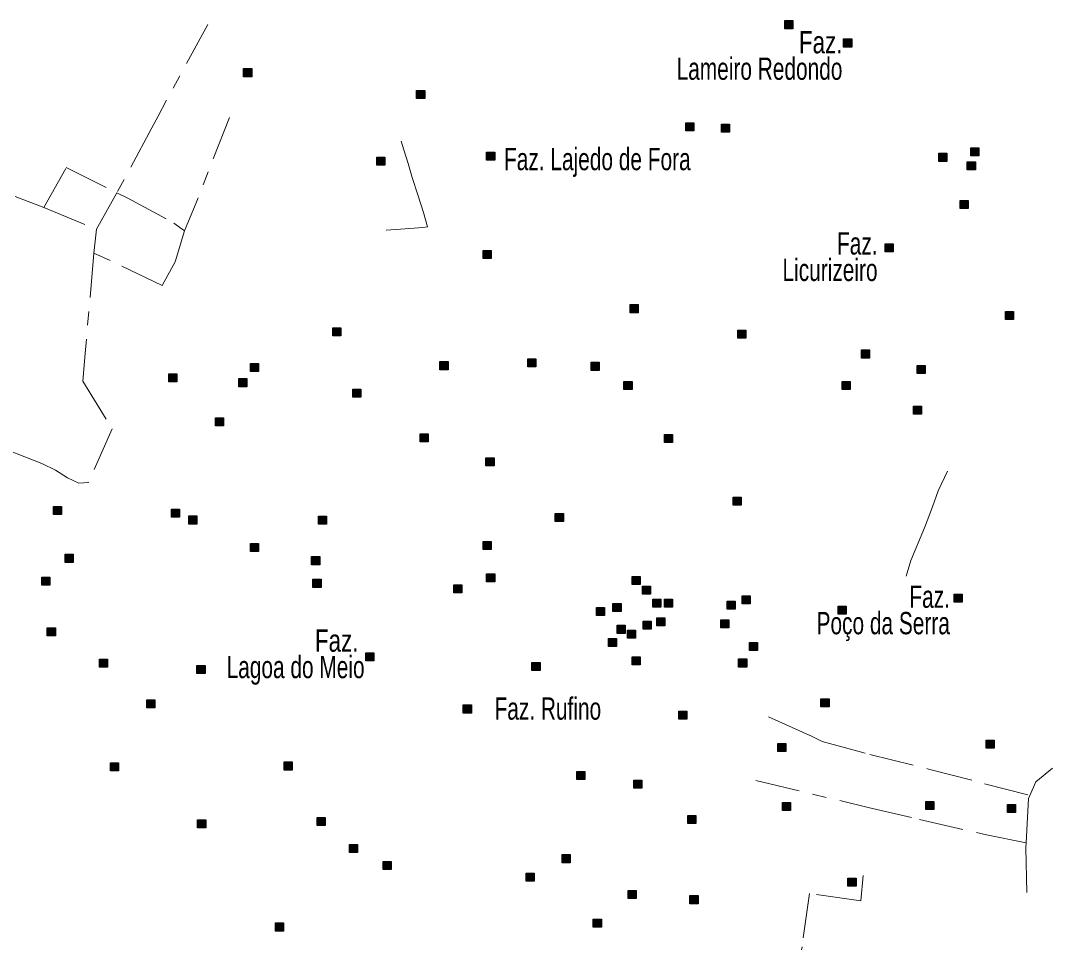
# Model space of a CAD drawing. Extents: x 445.4 to 500, y 8728.7 to 8784.
# Drawn here: x 492.59 to 500, y 8746.14 to 8752.76 of the extents above; entities that cross this region are included whole.
import ezdxf
from ezdxf.enums import TextEntityAlignment as Align

# ---------------------------------------------------------------- set-up
doc = ezdxf.new("R2010")
doc.units = 0
doc.header["$LTSCALE"] = 0.064
doc.linetypes.add('DOT_DASHED', pattern=[7.7, 5, -1.2, 0.3, -1.2])
doc.layers.add('2', color=7, linetype='Continuous', lineweight=25)
doc.layers.add('22', color=7, linetype='DOT_DASHED', lineweight=13)
doc.layers.add('61', color=7, linetype='Continuous')

msp = doc.modelspace()

# ---------------------------------------------------------------- hatches: boundary and pattern name
at = {"layer": '2'}
for points in [[(498.0778, 8752.7596), (498.1358, 8752.7596), (498.1358, 8752.7016), (498.0778, 8752.7016)], [(498.501, 8752.6281), (498.559, 8752.6281), (498.559, 8752.5701), (498.501, 8752.5701)], [(494.1928, 8752.4151), (494.2508, 8752.4151), (494.2508, 8752.3571), (494.1928, 8752.3571)], [(495.435, 8752.2582), (495.493, 8752.2582), (495.493, 8752.2002), (495.435, 8752.2002)], [(497.3673, 8752.0264), (497.4253, 8752.0264), (497.4253, 8751.9684), (497.3673, 8751.9684)], [(497.6236, 8752.0166), (497.6816, 8752.0166), (497.6816, 8751.9586), (497.6236, 8751.9586)], [(495.9378, 8751.8144), (495.9958, 8751.8144), (495.9958, 8751.7564), (495.9378, 8751.7564)], [(499.1851, 8751.8069), (499.2431, 8751.8069), (499.2431, 8751.7489), (499.1851, 8751.7489)], [(499.415, 8751.847), (499.473, 8751.847), (499.473, 8751.789), (499.415, 8751.789)], [(495.1491, 8751.7799), (495.2071, 8751.7799), (495.2071, 8751.7219), (495.1491, 8751.7219)], [(499.389, 8751.7454), (499.447, 8751.7454), (499.447, 8751.6874), (499.389, 8751.6874)], [(499.3374, 8751.468), (499.3954, 8751.468), (499.3954, 8751.41), (499.3374, 8751.41)], [(498.7985, 8751.1572), (498.8565, 8751.1572), (498.8565, 8751.0992), (498.7985, 8751.0992)], [(495.9132, 8751.1091), (495.9712, 8751.1091), (495.9712, 8751.0511), (495.9132, 8751.0511)], [(496.968, 8750.7195), (497.026, 8750.7195), (497.026, 8750.6615), (496.968, 8750.6615)], [(499.663, 8750.6703), (499.721, 8750.6703), (499.721, 8750.6123), (499.663, 8750.6123)], [(494.833, 8750.5535), (494.891, 8750.5535), (494.891, 8750.4955), (494.833, 8750.4955)], [(497.7419, 8750.5371), (497.7999, 8750.5371), (497.7999, 8750.4791), (497.7419, 8750.4791)], [(498.6292, 8750.394), (498.6872, 8750.394), (498.6872, 8750.336), (498.6292, 8750.336)], [(495.6026, 8750.3102), (495.6606, 8750.3102), (495.6606, 8750.2522), (495.6026, 8750.2522)], [(496.2336, 8750.3299), (496.2916, 8750.3299), (496.2916, 8750.2719), (496.2336, 8750.2719)], [(494.2421, 8750.2965), (494.3001, 8750.2965), (494.3001, 8750.2385), (494.2421, 8750.2385)], [(496.6871, 8750.3053), (496.7451, 8750.3053), (496.7451, 8750.2473), (496.6871, 8750.2473)], [(499.0283, 8750.2826), (499.0863, 8750.2826), (499.0863, 8750.2246), (499.0283, 8750.2246)], [(493.6555, 8750.2225), (493.7135, 8750.2225), (493.7135, 8750.1645), (493.6555, 8750.1645)], [(494.1583, 8750.188), (494.2163, 8750.188), (494.2163, 8750.13), (494.1583, 8750.13)], [(496.9237, 8750.1672), (496.9817, 8750.1672), (496.9817, 8750.1092), (496.9237, 8750.1092)], [(498.4912, 8750.1672), (498.5492, 8750.1672), (498.5492, 8750.1092), (498.4912, 8750.1092)], [(494.9766, 8750.1129), (495.0346, 8750.1129), (495.0346, 8750.0549), (494.9766, 8750.0549)], [(499.0028, 8749.9906), (499.0608, 8749.9906), (499.0608, 8749.9326), (499.0028, 8749.9326)], [(493.9907, 8749.9068), (494.0487, 8749.9068), (494.0487, 8749.8488), (493.9907, 8749.8488)], [(495.4597, 8749.7924), (495.5177, 8749.7924), (495.5177, 8749.7344), (495.4597, 8749.7344)], [(497.2145, 8749.7874), (497.2725, 8749.7874), (497.2725, 8749.7294), (497.2145, 8749.7294)], [(495.9329, 8749.6198), (495.9909, 8749.6198), (495.9909, 8749.5618), (495.9329, 8749.5618)], [(492.8274, 8749.2707), (492.8854, 8749.2707), (492.8854, 8749.2127), (492.8274, 8749.2127)], [(497.7081, 8749.337), (497.7661, 8749.337), (497.7661, 8749.279), (497.7081, 8749.279)], [(493.6752, 8749.2509), (493.7332, 8749.2509), (493.7332, 8749.1929), (493.6752, 8749.1929)], [(493.7985, 8749.2016), (493.8565, 8749.2016), (493.8565, 8749.1436), (493.7985, 8749.1436)], [(494.7302, 8749.2006), (494.7882, 8749.2006), (494.7882, 8749.1426), (494.7302, 8749.1426)], [(496.4307, 8749.2203), (496.4887, 8749.2203), (496.4887, 8749.1623), (496.4307, 8749.1623)], [(494.2421, 8749.0043), (494.3001, 8749.0043), (494.3001, 8748.9463), (494.2421, 8748.9463)], [(495.9132, 8749.0181), (495.9712, 8749.0181), (495.9712, 8748.9601), (495.9132, 8748.9601)], [(492.9115, 8748.9265), (492.9695, 8748.9265), (492.9695, 8748.8685), (492.9115, 8748.8685)], [(494.6809, 8748.9096), (494.7389, 8748.9096), (494.7389, 8748.8516), (494.6809, 8748.8516)], [(492.7436, 8748.7627), (492.8016, 8748.7627), (492.8016, 8748.7047), (492.7436, 8748.7047)], [(495.9378, 8748.7863), (495.9958, 8748.7863), (495.9958, 8748.7283), (495.9378, 8748.7283)], [(496.9828, 8748.7666), (497.0408, 8748.7666), (497.0408, 8748.7086), (496.9828, 8748.7086)], [(494.6907, 8748.7469), (494.7487, 8748.7469), (494.7487, 8748.6889), (494.6907, 8748.6889)], [(495.7012, 8748.7074), (495.7592, 8748.7074), (495.7592, 8748.6494), (495.7012, 8748.6494)], [(497.0568, 8748.6975), (497.1148, 8748.6975), (497.1148, 8748.6395), (497.0568, 8748.6395)], [(497.1307, 8748.6038), (497.1887, 8748.6038), (497.1887, 8748.5458), (497.1307, 8748.5458)], [(497.2145, 8748.6038), (497.2725, 8748.6038), (497.2725, 8748.5458), (497.2145, 8748.5458)], [(497.7715, 8748.6285), (497.8295, 8748.6285), (497.8295, 8748.5705), (497.7715, 8748.5705)], [(499.2946, 8748.6402), (499.3526, 8748.6402), (499.3526, 8748.5822), (499.2946, 8748.5822)], [(496.7265, 8748.5447), (496.7845, 8748.5447), (496.7845, 8748.4867), (496.7265, 8748.4867)], [(496.8448, 8748.5742), (496.9028, 8748.5742), (496.9028, 8748.5162), (496.8448, 8748.5162)], [(497.6649, 8748.5898), (497.7229, 8748.5898), (497.7229, 8748.5318), (497.6649, 8748.5318)], [(498.4616, 8748.5545), (498.5196, 8748.5545), (498.5196, 8748.4965), (498.4616, 8748.4965)], [(497.1603, 8748.4707), (497.2183, 8748.4707), (497.2183, 8748.4127), (497.1603, 8748.4127)], [(497.6187, 8748.4559), (497.6767, 8748.4559), (497.6767, 8748.3979), (497.6187, 8748.3979)], [(492.7831, 8748.3977), (492.8411, 8748.3977), (492.8411, 8748.3397), (492.7831, 8748.3397)], [(496.8744, 8748.4164), (496.9324, 8748.4164), (496.9324, 8748.3584), (496.8744, 8748.3584)], [(496.9483, 8748.3819), (497.0063, 8748.3819), (497.0063, 8748.3239), (496.9483, 8748.3239)], [(497.0617, 8748.446), (497.1197, 8748.446), (497.1197, 8748.388), (497.0617, 8748.388)], [(496.8133, 8748.3212), (496.8713, 8748.3212), (496.8713, 8748.2632), (496.8133, 8748.2632)], [(497.8257, 8748.2931), (497.8837, 8748.2931), (497.8837, 8748.2351), (497.8257, 8748.2351)], [(493.1577, 8748.1729), (493.2157, 8748.1729), (493.2157, 8748.1149), (493.1577, 8748.1149)], [(495.0703, 8748.2192), (495.1283, 8748.2192), (495.1283, 8748.1612), (495.0703, 8748.1612)], [(496.9828, 8748.1896), (497.0408, 8748.1896), (497.0408, 8748.1316), (496.9828, 8748.1316)], [(497.7469, 8748.1748), (497.8049, 8748.1748), (497.8049, 8748.1168), (497.7469, 8748.1168)], [(493.8576, 8748.1285), (493.9156, 8748.1285), (493.9156, 8748.0705), (493.8576, 8748.0705)], [(496.2632, 8748.1501), (496.3212, 8748.1501), (496.3212, 8748.0921), (496.2632, 8748.0921)], [(493.4978, 8747.8819), (493.5558, 8747.8819), (493.5558, 8747.8239), (493.4978, 8747.8239)], [(498.3384, 8747.8887), (498.3964, 8747.8887), (498.3964, 8747.8307), (498.3384, 8747.8307)], [(495.7702, 8747.8444), (495.8282, 8747.8444), (495.8282, 8747.7864), (495.7702, 8747.7864)], [(497.318, 8747.8), (497.376, 8747.8), (497.376, 8747.742), (497.318, 8747.742)], [(498.0278, 8747.5682), (498.0858, 8747.5682), (498.0858, 8747.5102), (498.0278, 8747.5102)], [(499.5244, 8747.5926), (499.5824, 8747.5926), (499.5824, 8747.5346), (499.5244, 8747.5346)], [(493.2365, 8747.4282), (493.2945, 8747.4282), (493.2945, 8747.3702), (493.2365, 8747.3702)], [(494.4837, 8747.435), (494.5417, 8747.435), (494.5417, 8747.377), (494.4837, 8747.377)], [(496.5854, 8747.366), (496.6434, 8747.366), (496.6434, 8747.308), (496.5854, 8747.308)], [(496.9938, 8747.3052), (497.0518, 8747.3052), (497.0518, 8747.2472), (496.9938, 8747.2472)], [(498.0623, 8747.1441), (498.1203, 8747.1441), (498.1203, 8747.0861), (498.0623, 8747.0861)], [(499.0903, 8747.151), (499.1483, 8747.151), (499.1483, 8747.093), (499.0903, 8747.093)], [(499.6776, 8747.129), (499.7356, 8747.129), (499.7356, 8747.071), (499.6776, 8747.071)], [(497.3828, 8747.0503), (497.4408, 8747.0503), (497.4408, 8746.9923), (497.3828, 8746.9923)], [(493.8626, 8747.0189), (493.9206, 8747.0189), (493.9206, 8746.9609), (493.8626, 8746.9609)], [(494.721, 8747.0366), (494.779, 8747.0366), (494.779, 8746.9786), (494.721, 8746.9786)], [(494.9535, 8746.8417), (495.0115, 8746.8417), (495.0115, 8746.7837), (494.9535, 8746.7837)], [(496.48, 8746.7692), (496.538, 8746.7692), (496.538, 8746.7112), (496.48, 8746.7112)], [(495.1935, 8746.7199), (495.2515, 8746.7199), (495.2515, 8746.6619), (495.1935, 8746.6619)], [(496.2206, 8746.6365), (496.2786, 8746.6365), (496.2786, 8746.5785), (496.2206, 8746.5785)], [(498.5322, 8746.5998), (498.5902, 8746.5998), (498.5902, 8746.5418), (498.5322, 8746.5418)], [(496.9532, 8746.5128), (497.0112, 8746.5128), (497.0112, 8746.4548), (496.9532, 8746.4548)], [(497.3976, 8746.4751), (497.4556, 8746.4751), (497.4556, 8746.4171), (497.3976, 8746.4171)], [(496.7037, 8746.3053), (496.7617, 8746.3053), (496.7617, 8746.2473), (496.7037, 8746.2473)], [(494.4212, 8746.2783), (494.4792, 8746.2783), (494.4792, 8746.2203), (494.4212, 8746.2203)]]:
    msp.add_hatch(color=256, dxfattribs=at).paths.add_polyline_path(points)

# ---------------------------------------------------------------- linework, layer by layer
for points in [[(498.0778, 8752.7596), (498.1358, 8752.7596), (498.1358, 8752.7016), (498.0778, 8752.7016)], [(498.501, 8752.6281), (498.559, 8752.6281), (498.559, 8752.5701), (498.501, 8752.5701)], [(494.1928, 8752.4151), (494.2508, 8752.4151), (494.2508, 8752.3571), (494.1928, 8752.3571)], [(495.435, 8752.2582), (495.493, 8752.2582), (495.493, 8752.2002), (495.435, 8752.2002)], [(497.3673, 8752.0264), (497.4253, 8752.0264), (497.4253, 8751.9684), (497.3673, 8751.9684)], [(497.6236, 8752.0166), (497.6816, 8752.0166), (497.6816, 8751.9586), (497.6236, 8751.9586)], [(495.9378, 8751.8144), (495.9958, 8751.8144), (495.9958, 8751.7564), (495.9378, 8751.7564)], [(499.1851, 8751.8069), (499.2431, 8751.8069), (499.2431, 8751.7489), (499.1851, 8751.7489)], [(499.415, 8751.847), (499.473, 8751.847), (499.473, 8751.789), (499.415, 8751.789)], [(495.1491, 8751.7799), (495.2071, 8751.7799), (495.2071, 8751.7219), (495.1491, 8751.7219)], [(499.389, 8751.7454), (499.447, 8751.7454), (499.447, 8751.6874), (499.389, 8751.6874)], [(499.3374, 8751.468), (499.3954, 8751.468), (499.3954, 8751.41), (499.3374, 8751.41)], [(498.7985, 8751.1572), (498.8565, 8751.1572), (498.8565, 8751.0992), (498.7985, 8751.0992)], [(495.9132, 8751.1091), (495.9712, 8751.1091), (495.9712, 8751.0511), (495.9132, 8751.0511)], [(496.968, 8750.7195), (497.026, 8750.7195), (497.026, 8750.6615), (496.968, 8750.6615)], [(499.663, 8750.6703), (499.721, 8750.6703), (499.721, 8750.6123), (499.663, 8750.6123)], [(494.833, 8750.5535), (494.891, 8750.5535), (494.891, 8750.4955), (494.833, 8750.4955)], [(497.7419, 8750.5371), (497.7999, 8750.5371), (497.7999, 8750.4791), (497.7419, 8750.4791)], [(498.6292, 8750.394), (498.6872, 8750.394), (498.6872, 8750.336), (498.6292, 8750.336)], [(495.6026, 8750.3102), (495.6606, 8750.3102), (495.6606, 8750.2522), (495.6026, 8750.2522)], [(496.2336, 8750.3299), (496.2916, 8750.3299), (496.2916, 8750.2719), (496.2336, 8750.2719)], [(494.2421, 8750.2965), (494.3001, 8750.2965), (494.3001, 8750.2385), (494.2421, 8750.2385)], [(496.6871, 8750.3053), (496.7451, 8750.3053), (496.7451, 8750.2473), (496.6871, 8750.2473)], [(499.0283, 8750.2826), (499.0863, 8750.2826), (499.0863, 8750.2246), (499.0283, 8750.2246)], [(493.6555, 8750.2225), (493.7135, 8750.2225), (493.7135, 8750.1645), (493.6555, 8750.1645)], [(494.1583, 8750.188), (494.2163, 8750.188), (494.2163, 8750.13), (494.1583, 8750.13)], [(496.9237, 8750.1672), (496.9817, 8750.1672), (496.9817, 8750.1092), (496.9237, 8750.1092)], [(498.4912, 8750.1672), (498.5492, 8750.1672), (498.5492, 8750.1092), (498.4912, 8750.1092)], [(494.9766, 8750.1129), (495.0346, 8750.1129), (495.0346, 8750.0549), (494.9766, 8750.0549)], [(499.0028, 8749.9906), (499.0608, 8749.9906), (499.0608, 8749.9326), (499.0028, 8749.9326)], [(493.9907, 8749.9068), (494.0487, 8749.9068), (494.0487, 8749.8488), (493.9907, 8749.8488)], [(495.4597, 8749.7924), (495.5177, 8749.7924), (495.5177, 8749.7344), (495.4597, 8749.7344)], [(497.2145, 8749.7874), (497.2725, 8749.7874), (497.2725, 8749.7294), (497.2145, 8749.7294)], [(495.9329, 8749.6198), (495.9909, 8749.6198), (495.9909, 8749.5618), (495.9329, 8749.5618)], [(492.8274, 8749.2707), (492.8854, 8749.2707), (492.8854, 8749.2127), (492.8274, 8749.2127)], [(497.7081, 8749.337), (497.7661, 8749.337), (497.7661, 8749.279), (497.7081, 8749.279)], [(493.6752, 8749.2509), (493.7332, 8749.2509), (493.7332, 8749.1929), (493.6752, 8749.1929)], [(493.7985, 8749.2016), (493.8565, 8749.2016), (493.8565, 8749.1436), (493.7985, 8749.1436)], [(494.7302, 8749.2006), (494.7882, 8749.2006), (494.7882, 8749.1426), (494.7302, 8749.1426)], [(496.4307, 8749.2203), (496.4887, 8749.2203), (496.4887, 8749.1623), (496.4307, 8749.1623)], [(494.2421, 8749.0043), (494.3001, 8749.0043), (494.3001, 8748.9463), (494.2421, 8748.9463)], [(495.9132, 8749.0181), (495.9712, 8749.0181), (495.9712, 8748.9601), (495.9132, 8748.9601)], [(492.9115, 8748.9265), (492.9695, 8748.9265), (492.9695, 8748.8685), (492.9115, 8748.8685)], [(494.6809, 8748.9096), (494.7389, 8748.9096), (494.7389, 8748.8516), (494.6809, 8748.8516)], [(492.7436, 8748.7627), (492.8016, 8748.7627), (492.8016, 8748.7047), (492.7436, 8748.7047)], [(495.9378, 8748.7863), (495.9958, 8748.7863), (495.9958, 8748.7283), (495.9378, 8748.7283)], [(496.9828, 8748.7666), (497.0408, 8748.7666), (497.0408, 8748.7086), (496.9828, 8748.7086)], [(494.6907, 8748.7469), (494.7487, 8748.7469), (494.7487, 8748.6889), (494.6907, 8748.6889)], [(495.7012, 8748.7074), (495.7592, 8748.7074), (495.7592, 8748.6494), (495.7012, 8748.6494)], [(497.0568, 8748.6975), (497.1148, 8748.6975), (497.1148, 8748.6395), (497.0568, 8748.6395)], [(497.1307, 8748.6038), (497.1887, 8748.6038), (497.1887, 8748.5458), (497.1307, 8748.5458)], [(497.2145, 8748.6038), (497.2725, 8748.6038), (497.2725, 8748.5458), (497.2145, 8748.5458)], [(497.7715, 8748.6285), (497.8295, 8748.6285), (497.8295, 8748.5705), (497.7715, 8748.5705)], [(499.2946, 8748.6402), (499.3526, 8748.6402), (499.3526, 8748.5822), (499.2946, 8748.5822)], [(496.7265, 8748.5447), (496.7845, 8748.5447), (496.7845, 8748.4867), (496.7265, 8748.4867)], [(496.8448, 8748.5742), (496.9028, 8748.5742), (496.9028, 8748.5162), (496.8448, 8748.5162)], [(497.6649, 8748.5898), (497.7229, 8748.5898), (497.7229, 8748.5318), (497.6649, 8748.5318)], [(498.4616, 8748.5545), (498.5196, 8748.5545), (498.5196, 8748.4965), (498.4616, 8748.4965)], [(497.1603, 8748.4707), (497.2183, 8748.4707), (497.2183, 8748.4127), (497.1603, 8748.4127)], [(497.6187, 8748.4559), (497.6767, 8748.4559), (497.6767, 8748.3979), (497.6187, 8748.3979)], [(492.7831, 8748.3977), (492.8411, 8748.3977), (492.8411, 8748.3397), (492.7831, 8748.3397)], [(496.8744, 8748.4164), (496.9324, 8748.4164), (496.9324, 8748.3584), (496.8744, 8748.3584)], [(496.9483, 8748.3819), (497.0063, 8748.3819), (497.0063, 8748.3239), (496.9483, 8748.3239)], [(497.0617, 8748.446), (497.1197, 8748.446), (497.1197, 8748.388), (497.0617, 8748.388)], [(496.8133, 8748.3212), (496.8713, 8748.3212), (496.8713, 8748.2632), (496.8133, 8748.2632)], [(497.8257, 8748.2931), (497.8837, 8748.2931), (497.8837, 8748.2351), (497.8257, 8748.2351)], [(493.1577, 8748.1729), (493.2157, 8748.1729), (493.2157, 8748.1149), (493.1577, 8748.1149)], [(495.0703, 8748.2192), (495.1283, 8748.2192), (495.1283, 8748.1612), (495.0703, 8748.1612)], [(496.9828, 8748.1896), (497.0408, 8748.1896), (497.0408, 8748.1316), (496.9828, 8748.1316)], [(497.7469, 8748.1748), (497.8049, 8748.1748), (497.8049, 8748.1168), (497.7469, 8748.1168)], [(493.8576, 8748.1285), (493.9156, 8748.1285), (493.9156, 8748.0705), (493.8576, 8748.0705)], [(496.2632, 8748.1501), (496.3212, 8748.1501), (496.3212, 8748.0921), (496.2632, 8748.0921)], [(493.4978, 8747.8819), (493.5558, 8747.8819), (493.5558, 8747.8239), (493.4978, 8747.8239)], [(498.3384, 8747.8887), (498.3964, 8747.8887), (498.3964, 8747.8307), (498.3384, 8747.8307)], [(495.7702, 8747.8444), (495.8282, 8747.8444), (495.8282, 8747.7864), (495.7702, 8747.7864)], [(497.318, 8747.8), (497.376, 8747.8), (497.376, 8747.742), (497.318, 8747.742)], [(498.0278, 8747.5682), (498.0858, 8747.5682), (498.0858, 8747.5102), (498.0278, 8747.5102)], [(499.5244, 8747.5926), (499.5824, 8747.5926), (499.5824, 8747.5346), (499.5244, 8747.5346)], [(493.2365, 8747.4282), (493.2945, 8747.4282), (493.2945, 8747.3702), (493.2365, 8747.3702)], [(494.4837, 8747.435), (494.5417, 8747.435), (494.5417, 8747.377), (494.4837, 8747.377)], [(496.5854, 8747.366), (496.6434, 8747.366), (496.6434, 8747.308), (496.5854, 8747.308)], [(496.9938, 8747.3052), (497.0518, 8747.3052), (497.0518, 8747.2472), (496.9938, 8747.2472)], [(498.0623, 8747.1441), (498.1203, 8747.1441), (498.1203, 8747.0861), (498.0623, 8747.0861)], [(499.0903, 8747.151), (499.1483, 8747.151), (499.1483, 8747.093), (499.0903, 8747.093)], [(499.6776, 8747.129), (499.7356, 8747.129), (499.7356, 8747.071), (499.6776, 8747.071)], [(497.3828, 8747.0503), (497.4408, 8747.0503), (497.4408, 8746.9923), (497.3828, 8746.9923)], [(493.8626, 8747.0189), (493.9206, 8747.0189), (493.9206, 8746.9609), (493.8626, 8746.9609)], [(494.721, 8747.0366), (494.779, 8747.0366), (494.779, 8746.9786), (494.721, 8746.9786)], [(494.9535, 8746.8417), (495.0115, 8746.8417), (495.0115, 8746.7837), (494.9535, 8746.7837)], [(496.48, 8746.7692), (496.538, 8746.7692), (496.538, 8746.7112), (496.48, 8746.7112)], [(495.1935, 8746.7199), (495.2515, 8746.7199), (495.2515, 8746.6619), (495.1935, 8746.6619)], [(496.2206, 8746.6365), (496.2786, 8746.6365), (496.2786, 8746.5785), (496.2206, 8746.5785)], [(498.5322, 8746.5998), (498.5902, 8746.5998), (498.5902, 8746.5418), (498.5322, 8746.5418)], [(496.9532, 8746.5128), (497.0112, 8746.5128), (497.0112, 8746.4548), (496.9532, 8746.4548)], [(497.3976, 8746.4751), (497.4556, 8746.4751), (497.4556, 8746.4171), (497.3976, 8746.4171)], [(496.7037, 8746.3053), (496.7617, 8746.3053), (496.7617, 8746.2473), (496.7037, 8746.2473)], [(494.4212, 8746.2783), (494.4792, 8746.2783), (494.4792, 8746.2203), (494.4212, 8746.2203)]]:
    msp.add_lwpolyline(points, close=True, dxfattribs=at)
at = {"layer": '22'}
for points in [[(493.9347, 8752.7327), (493.5783, 8752.0733), (493.5335, 8751.9893), (493.2824, 8751.5236), (493.2823, 8751.5234)], [(494.0914, 8752.0644), (493.8568, 8751.4637), (493.767, 8751.2503)], [(491.4786, 8751.9154), (491.9736, 8751.7188), (492.7571, 8751.4183), (493.1361, 8751.2616)], [(495.216, 8751.2534), (495.3861, 8751.2657), (495.4794, 8751.2735), (495.5131, 8751.2786), (495.4846, 8751.3826), (495.4431, 8751.5073), (495.4017, 8751.632), (495.3732, 8751.7334), (495.3421, 8751.8321), (495.3228, 8751.8936)], [(492.7571, 8751.4183), (492.9195, 8751.7045), (493.2823, 8751.5234)], [(493.2823, 8751.5234), (493.1361, 8751.2616), (493.1177, 8751.0897)], [(493.2823, 8751.5234), (493.3557, 8751.4867), (493.6921, 8751.3058), (493.767, 8751.2503)], [(493.767, 8751.2503), (493.7011, 8751.0282), (493.6075, 8750.8581), (493.2338, 8751.0359), (493.1177, 8751.0897)], [(493.1177, 8751.0897), (493.0549, 8750.3687), (493.0391, 8750.1694), (493.2494, 8749.8272), (493.0772, 8749.4422), (493.0086, 8749.4374), (492.929, 8749.4764), (492.8412, 8749.5317), (492.7432, 8749.5783), (491.9959, 8749.8735), (491.9016, 8749.9117), (491.8634, 8749.9297), (491.7302, 8749.9859), (491.2298, 8750.1898), (490.5897, 8750.4468)], [(498.95, 8748.77), (498.984, 8748.8824), (499.0825, 8749.1174), (499.1402, 8749.2673), (499.181, 8749.3831), (499.2465, 8749.5237)], [(497.9615, 8747.7599), (498.2551, 8747.6277), (498.3473, 8747.5816), (498.6899, 8747.4895), (499.1116, 8747.3842), (499.5135, 8747.279), (499.839, 8747.1945)], [(500, 8747.3908), (499.8824, 8747.2921), (499.839, 8747.1945)], [(497.8701, 8747.3023), (498.6768, 8747.1079), (499.0457, 8747.0223), (499.5267, 8746.9105), (499.8119, 8746.853)], [(499.839, 8747.1945), (499.8297, 8747.1737), (499.8119, 8746.853)], [(499.8119, 8746.853), (499.81, 8746.8184), (499.8195, 8746.4068)], [(498.6405, 8746.6201), (498.6241, 8746.4367), (498.2551, 8746.4894), (498.2024, 8746.1078), (498.1904, 8746.0518)]]:
    msp.add_lwpolyline(points, dxfattribs=at)

# ---------------------------------------------------------------- texts
at = {"layer": '61'}
for s, width, p in [('                    Faz.', 0.75, (498.4924, 8752.5247)), ('Lameiro Redondo', 0.7, (498.4924, 8752.3347)), ('           Faz.', 0.7, (498.7447, 8751.0794)), ('Licurizeiro', 0.7, (498.7447, 8750.8894)), ('               Faz.', 0.7, (499.2641, 8748.5421)), ('Poço da Serra', 0.7, (499.2641, 8748.3521)), ('                Faz. ', 0.75, (495.0613, 8748.227)), ('Lagoa do Meio', 0.7, (495.0613, 8748.037))]:
    msp.add_text(s, height=0.16, dxfattribs=dict(at, width=width)).set_placement(p, align=Align.RIGHT)
at = {"layer": '61', "width": 0.7}
for s, p in [('Faz. Lajedo de Fora', (496.0624, 8751.6853)), ('Faz. Rufino', (495.9942, 8747.7386))]:
    msp.add_text(s, height=0.16, dxfattribs=at).set_placement(p)

doc.saveas('drawing.dxf')
